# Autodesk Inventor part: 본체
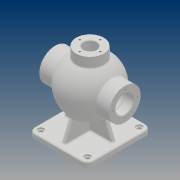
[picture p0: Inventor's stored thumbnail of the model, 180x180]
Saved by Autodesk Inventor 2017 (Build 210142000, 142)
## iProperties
Part Number: 본체
Material: 일반
Document SubType Name: Modeling
Designer: 13
Density: 1 g/cm^3
Appearance: 기본값
Author: 13
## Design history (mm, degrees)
sketch "스케치2"
  geometry: L1 (68, 0)-(-68, 0); L2 (68, 17.5)-(39.278, 17.5); L3 (-68, 17.5)-(-68, 31); L4 (-68, 31)-(-42.988, 31); L5 (42.988, 31)-(68, 31); L6 (68, 31)-(68, 17.5); L7 (-39.278, 17.5)-(-50.25, 17.5); L8 (-50.25, 17.5)-(-50.25, 18.5); L9 (-50.25, 18.5)-(-52, 18.5); L10 (-52, 18.5)-(-52, 17.5); L11 (-52, 17.5)-(-68, 17.5); A1 r 43 centre (0, 0) between (39.278, 17.5) and (-39.278, 17.5); A2 r 53 centre (0, 0) between (42.988, 31) and (-42.988, 31); 2 further points
  constraints: 22 end point, 6 horizontal, 5 point on line, 4 point on circle, 4 vertical, 3 coincident, 2 centre point, 1 midpoint
  dimensions: "d0" = 136 distance of L1.start L1.end; "d1" = 35 diameter of L2 L1; "d2" = 62 diameter of L5 L1; "d4" = 43 radius of A1; "d6" = 53 radius of A2; "d33" = 1.75 distance of L8.end L9.end; "d34" = 37 diameter of L9 L1; "d35" = 35 diameter of L7 L1; "d36" = 16 distance between parallel lines of L3 L10
revolve "회전1" sketch "스케치2" stored, may be unused: angle "d7" = 90 deg
node "작업 평면1"
sketch "스케치3"
  geometry: L1 (-57.5, 62.5)-(57.5, 62.5); L2 (57.5, 62.5)-(57.5, -62.5); L3 (57.5, -62.5)-(-57.5, -62.5); L4 (-57.5, -62.5)-(-57.5, 62.5); L5 (-57.5, 62.5)-(57.5, -62.5); L6 (57.5, 62.5)-(-57.5, -62.5); 1 further point
  constraints: 12 end point, 2 midpoint, 2 parallel, 1 horizontal, 1 perpendicular
  dimensions: "d9" = 115 distance of L2.end L3.end; "d10" = 125 distance of L1.end L2.end
extrude "돌출1" join sketch "스케치3" distance "d11" = 10; taper "d12" = 0 deg
sketch "스케치5"
  geometry: L1 (-4, -52.5)-(4, -52.5); L2 (4, -52.5)-(4, 52.5); L3 (4, 52.5)-(-4, 52.5); L4 (-4, 52.5)-(-4, -52.5); L5 (-4, -52.5)-(4, 52.5); L6 (4, -52.5)-(-4, 52.5); L7 (57.5, -62.5)-(-57.5, -62.5) reference; 1 further point
  constraints: 12 end point, 2 midpoint, 2 parallel, 1 horizontal, 1 perpendicular
  dimensions: "d15" = 8 distance of L2.end L3.end; "d16" = 10 distance between parallel lines of L7 L1
extrude "돌출2" join sketch "스케치5" stored distance "d17" = 10; taper "d18" = 0 deg
feature "면 기울기1" dims angle "d19" = 22 deg
feature "면 기울기2" dims angle "d20" = 22 deg
sketch "스케치6"
  geometry: L1 (-47.5, -4)-(47.5, -4); L2 (47.5, -4)-(47.5, 4); L3 (47.5, 4)-(-47.5, 4); L4 (-47.5, 4)-(-47.5, -4); L5 (-47.5, -4)-(47.5, 4); L6 (47.5, -4)-(-47.5, 4); L7 (-57.5, -62.5)-(-57.5, 62.5) reference; 1 further point
  constraints: 12 end point, 2 midpoint, 2 parallel, 1 horizontal, 1 perpendicular
  dimensions: "d21" = 8 distance of L1.end L2.end; "d22" = 10 distance between parallel lines of L7 L4
extrude "돌출3" join sketch "스케치6" stored distance "d23" = 10; taper "d24" = 0 deg
feature "면 기울기3" dims angle "d25" = 22 deg
node "작업 평면2"
sketch "스케치7"
  geometry: C1 r 27 at (0, 0); 1 further point
  constraints: 1 centre point, 1 coincident
  dimensions: "d27" = 54 diameter of C1
extrude "돌출4" join sketch "스케치7" stored distance "d28" = 10; taper "d29" = 0 deg
sketch "스케치8"
  geometry: C1 r 13 at (0, 0); 1 further point
  constraints: 1 centre point, 1 coincident
  dimensions: "d30" = 26 diameter of C1
extrude "돌출5" cut sketch "스케치8" distance "d31" = 30; taper "d32" = 0 deg
fillet "모깎기1" dims "d37" = 12
hole "구멍1" diameter "d40" = 8; stored, may be unused: countersink angle "d44" = 90 deg, drill point angle "d46" = 118 deg; dims "d38" = 10, "d39" = 10, "d41" = 6, "d42" = 12, "d43" = 3, "d45" = 8
hole "구멍2" diameter "d49" = 8; stored, may be unused: countersink angle "d53" = 90 deg, drill point angle "d55" = 118 deg; dims "d47" = 10, "d48" = 10, "d50" = 6, "d51" = 12, "d52" = 3, "d54" = 8
hole "구멍3" diameter "d58" = 8; stored, may be unused: countersink angle "d62" = 90 deg, drill point angle "d64" = 118 deg; dims "d56" = 10, "d57" = 10, "d59" = 6, "d60" = 12, "d61" = 3, "d63" = 8
hole "구멍4" diameter "d67" = 8; stored, may be unused: countersink angle "d71" = 90 deg, drill point angle "d73" = 118 deg; dims "d65" = 10, "d66" = 10, "d68" = 6, "d69" = 12, "d70" = 3, "d72" = 8
sketch "스케치9"
  geometry: 2 further points
  constraints: 1 horizontal alignment
  dimensions: "d74" = 24 distance of point (0, 0) point (-24, 0)
hole "구멍5" sketch "스케치9" at (-24, 0) diameter "d75" = 3.242; stored, may be unused: countersink angle "d79" = 90 deg, drill point angle "d81" = 118 deg; dims "d76" = 16, "d77" = 12, "d78" = 3, "d80" = 19
sketch "스케치10"
  geometry: 2 further points
  constraints: 1 horizontal alignment
  dimensions: "d85" = 22.5 distance of point (0, 0) point (22.5, 0)
hole "구멍6" sketch "스케치10" at (22.5, 0) diameter "d86" = 3.242; stored, may be unused: countersink angle "d90" = 90 deg, drill point angle "d92" = 118 deg; dims "d87" = 12, "d88" = 12, "d89" = 3, "d91" = 15
sketch "스케치11"
  geometry: 2 further points
  constraints: 1 horizontal alignment
  dimensions: "d93" = 20 distance of point (20, 0) point (0, 0)
hole "구멍7" sketch "스케치11" at (20, 0) diameter "d94" = 3.242; stored, may be unused: countersink angle "d98" = 90 deg, drill point angle "d100" = 118 deg; dims "d95" = 9, "d96" = 12, "d97" = 3, "d99" = 11
chamfer "모따기1" distance "d107" = 1; stored, may be unused: second distance "d108" = 2, angle "d109" = 45 deg
chamfer "모따기2" distance "d110" = 1; stored, may be unused: second distance "d111" = 2, angle "d112" = 45 deg
fillet "모깎기2" dims "d113" = 3
fillet "모깎기3" dims "d114" = 3
fillet "모깎기4" dims "d115" = 3
fillet "모깎기5" dims "d116" = 3
fillet "모깎기6" dims "d117" = 3
fillet "모깎기7" dims "d118" = 3
node "작업 평면3"
sketch "스케치12"
  geometry: L1 (27, 65)-(-27, 65) reference; L2 (-27, 65)-(-27, 47.286) reference; 2 further points
  constraints: 1 other
  dimensions: "d120" = 10 distance from line of L1 point (0, 55); "d121" = 27 distance from line of L2 point (0, 55)
feature "엠보싱1" sketch "스케치12" dims "d0" = 136, "d1" = 35, "d2" = 62, "d4" = 43, "d6" = 53, "d33" = 1.75, "d34" = 37, "d35" = 35, "d36" = 16, "d122" = 0.5, "d123" = 0
node "솔리드1"
pattern_circular "원형 패턴1" dims angle "d83" = 360 deg
pattern_circular "원형 패턴2" dims angle "d102" = 360 deg
pattern_circular "원형 패턴3" dims angle "d105" = 360 deg
other parameters: "d8" = -85
